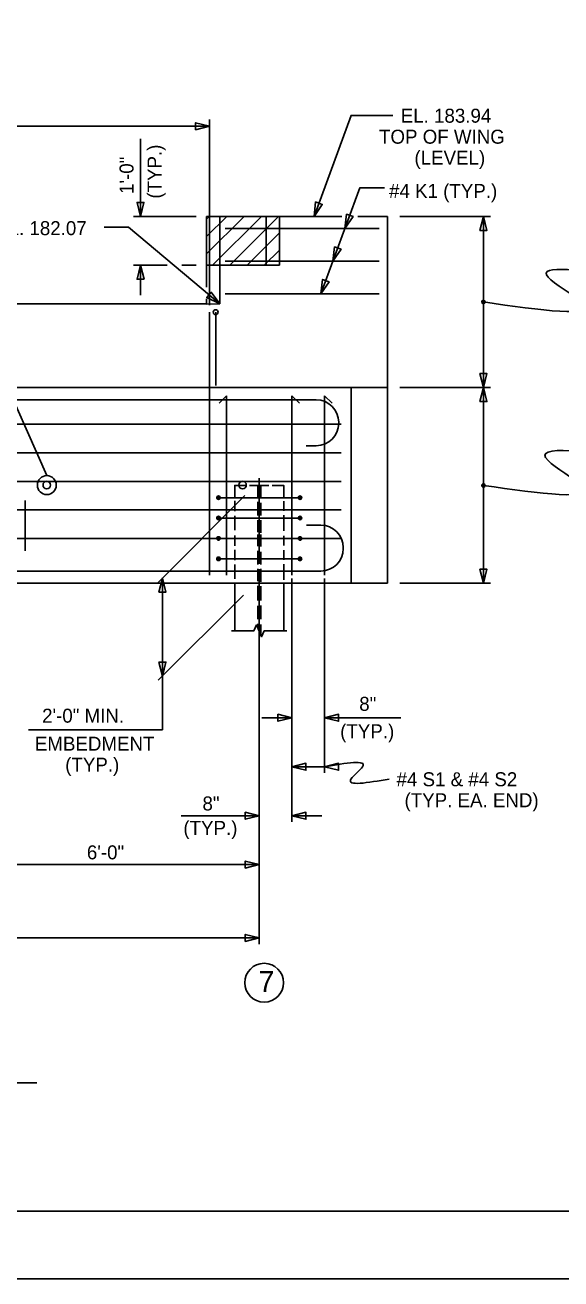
# Model space of a CAD drawing. Extents: x -41 to 191, y -168 to 6.
# Drawn here: x 160.78 to 171.73, y -50.47 to -24.84 of the extents above; entities that cross this region are included whole.
import ezdxf

# ---------------------------------------------------------------- set-up
doc = ezdxf.new("R2010")
doc.units = 0
for name, color, linetype in [('Arrowhead Terminators CELL', 7, 'Continuous'), ('Dimension Lines', 7, 'Continuous'), ('Dimension Lines CELL', 7, 'Continuous'), ('Mis Object Lines', 7, 'Continuous'), ('Plan Sheet CELL', 7, 'Continuous'), ('Plot Shape CELL', 7, 'Continuous'), ('Rebar Lines', 7, 'Continuous'), ('Rebar Lines CELL', 7, 'Continuous'), ('Sub End Bent Cap Lines CELL', 7, 'Continuous'), ('Text', 7, 'Continuous'), ('Title Text', 7, 'Continuous')]:
    doc.layers.add(name, color=color, linetype=linetype)

# ---------------------------------------------------------------- blocks, each defined once
blk = doc.blocks.new('AH')
at = {"layer": 'Sub End Bent Cap Lines CELL'}
blk.add_lwpolyline([(0, 0), (-1.25, 0.31), (-1.25, -0.31)], close=True, dxfattribs=at)

msp = doc.modelspace()

# ---------------------------------------------------------------- linework, layer by layer
at = {"layer": 'Arrowhead Terminators CELL'}
for points in [[(164.551, -26.909), (164.265, -26.98), (164.265, -26.837)], [(166.687, -28.749), (166.719, -28.455), (166.853, -28.505)], [(167.318, -28.999), (167.35, -28.705), (167.484, -28.755)], [(167.073, -29.665), (167.105, -29.372), (167.239, -29.421)], [(163.14, -29.749), (163.212, -30.036), (163.069, -30.036)], [(166.828, -30.332), (166.86, -30.039), (166.994, -30.088)], [(164.759, -30.54), (164.494, -30.41), (164.587, -30.301)], [(170.147, -32.249), (170.219, -31.962), (170.075, -31.962)], [(170.147, -32.249), (170.075, -32.535), (170.219, -32.535)], [(170.147, -36.249), (170.219, -35.962), (170.075, -35.962)], [(163.587, -36.142), (163.516, -36.428), (163.659, -36.428)], [(163.587, -38.144), (163.659, -37.858), (163.516, -37.858)], [(166.233, -38.999), (165.947, -39.07), (165.947, -38.927)], [(166.9, -38.999), (167.186, -39.07), (167.186, -38.927)], [(166.233, -39.999), (166.519, -40.07), (166.519, -39.927)], [(166.9, -39.999), (167.186, -40.07), (167.186, -39.927)], [(165.566, -40.999), (165.28, -41.07), (165.28, -40.927)], [(166.233, -40.999), (166.519, -40.927), (166.519, -41.07)], [(165.566, -41.998), (165.28, -41.926), (165.28, -42.069)], [(165.566, -43.498), (165.28, -43.426), (165.28, -43.569)]]:
    msp.add_lwpolyline(points, close=True, dxfattribs=at)
at = {"layer": 'Dimension Lines'}
for p, q in [((148.448, -26.909), (164.521, -26.909)), ((149.531, -26.909), (164.551, -26.909)), ((164.551, -30.564), (164.551, -26.766)), ((163.14, -27.166), (163.14, -28.749)), ((164.278, -28.749), (162.997, -28.749)), ((164.491, -29.16), (164.903, -28.749)), ((164.491, -28.806), (164.549, -28.749)), ((164.491, -29.513), (165.256, -28.749)), ((164.61, -29.749), (165.61, -28.749)), ((164.963, -29.749), (165.963, -28.749)), ((168.442, -28.749), (170.29, -28.749)), ((170.147, -28.749), (170.147, -32.249)), ((165.317, -29.749), (165.979, -29.086)), ((165.67, -29.749), (165.979, -29.44)), ((163.687, -29.749), (162.997, -29.749)), ((163.14, -29.749), (163.14, -30.357)), ((164.278, -29.749), (163.981, -29.749)), ((160.22, -31.784), (161.225, -34.049)), ((168.442, -32.249), (170.29, -32.249)), ((170.147, -36.249), (170.147, -32.249)), ((160.781, -35.588), (160.781, -34.56)), ((165.272, -34.457), (163.499, -36.23)), ((163.587, -39.241), (163.587, -36.142)), ((165.566, -36.249), (165.566, -43.623)), ((166.233, -36.154), (166.233, -41.124)), ((166.9, -36.154), (166.9, -40.124)), ((168.442, -36.249), (170.29, -36.249)), ((165.242, -36.489), (163.499, -38.232)), ((166.233, -38.999), (165.618, -38.999)), ((166.9, -38.999), (168.463, -38.999)), ((160.853, -39.241), (163.587, -39.241)), ((166.9, -39.999), (166.233, -39.999)), ((165.566, -40.999), (163.968, -40.999)), ((166.848, -40.999), (166.233, -40.999)), ((159.566, -41.998), (165.566, -41.998)), ((165.566, -43.498), (159.566, -43.498)), ((161.023, -46.457), (136.321, -46.457))]:
    msp.add_line(p, q, dxfattribs=at)
for points in [[(166.687, -28.749), (167.444, -26.687), (168.299, -26.687)], [(166.828, -30.332), (167.624, -28.166), (168.124, -28.166)], [(164.759, -30.54), (162.896, -28.97), (162.396, -28.97)]]:
    msp.add_lwpolyline(points, dxfattribs=at)
for centre, radius in [((161.225, -34.242), 0.193), ((165.666, -44.413), 0.397)]:
    msp.add_circle(centre, radius, dxfattribs=at)
for points in [[(173.186, -29.991), (171.467, -29.991), (172.144, -30.499), (170.147, -30.499)], [(173.587, -33.741), (171.467, -33.741), (172.144, -34.249), (170.147, -34.249)], [(166.9, -39.999), (167.678, -39.999), (167.441, -40.249), (168.22, -40.249)]]:
    msp.add_spline(points, degree=3, dxfattribs=at)
at = {"layer": 'Dimension Lines CELL'}
for centre in [(170.147, -30.499), (170.147, -34.249)]:
    msp.add_circle(centre, 0.0353, dxfattribs=at)
at = {"layer": 'Mis Object Lines'}
for p, q in [((164.491, -28.749), (167.252, -28.749)), ((164.491, -30.195), (164.491, -28.749)), ((164.759, -30.54), (164.759, -28.748)), ((165.711, -29.748), (165.711, -28.748)), ((165.979, -29.748), (165.979, -28.748)), ((168.185, -28.749), (167.584, -28.749)), ((168.185, -28.749), (168.185, -36.249)), ((164.491, -29.749), (165.711, -29.749)), ((165.711, -29.749), (165.979, -29.748)), ((168.185, -29.749), (168.185, -36.249)), ((164.491, -30.54), (164.491, -30.437)), ((137.623, -30.54), (164.491, -30.54)), ((164.491, -30.541), (164.759, -30.54)), ((147.948, -32.249), (168.185, -32.249)), ((167.448, -32.249), (167.448, -36.249)), ((133.764, -36.249), (168.185, -36.249))]:
    msp.add_line(p, q, dxfattribs=at)
at = {"layer": 'Plan Sheet CELL'}
msp.add_line((118.128, -49.079), (191.409, -49.079), dxfattribs=at)
at = {"layer": 'Plot Shape CELL'}
msp.add_lwpolyline([(115.715, -0.087), (191.429, -0.087), (191.429, -50.467), (115.715, -50.467)], close=True, dxfattribs=at)
at = {"layer": 'Rebar Lines'}
for p, q in [((168.018, -28.999), (164.869, -28.999)), ((168.018, -29.665), (164.869, -29.665)), ((168.018, -30.332), (164.869, -30.332)), ((164.551, -30.938), (164.551, -30.707)), ((164.676, -30.955), (164.676, -30.707)), ((164.551, -36.082), (164.551, -30.938)), ((164.676, -32.207), (164.676, -30.955)), ((127.69, -32.5), (166.732, -32.5)), ((164.9, -32.415), (164.746, -32.569)), ((164.9, -36.082), (164.9, -32.415)), ((166.387, -32.569), (166.233, -32.415)), ((166.233, -32.415), (166.233, -36.082)), ((166.9, -32.415), (166.9, -36.082)), ((167.053, -32.569), (166.9, -32.415)), ((149.253, -32.999), (167.24, -32.999)), ((149.253, -33.582), (167.24, -33.582)), ((149.253, -34.165), (167.24, -34.165)), ((165.535, -34.491), (165.535, -34.249)), ((165.566, -34.097), (165.566, -35.854)), ((165.598, -34.497), (165.598, -34.249)), ((165.535, -34.863), (165.535, -34.584)), ((149.253, -34.749), (167.24, -34.749)), ((165.598, -34.863), (165.598, -34.607)), ((165.535, -35.206), (165.535, -34.956)), ((165.598, -35.217), (165.598, -34.956)), ((149.253, -35.332), (167.24, -35.332)), ((165.535, -35.491), (165.535, -35.249)), ((165.598, -35.497), (165.598, -35.249)), ((165.535, -35.863), (165.535, -35.584)), ((165.598, -35.863), (165.598, -35.607)), ((127.69, -35.999), (166.825, -35.999)), ((165.535, -36.206), (165.535, -35.956)), ((165.566, -35.958), (165.566, -36.249)), ((165.598, -36.217), (165.598, -35.956)), ((165.066, -36.266), (165.066, -37.218)), ((165.535, -36.601), (165.535, -36.304)), ((165.566, -36.318), (165.566, -37.524)), ((165.598, -36.601), (165.598, -36.31)), ((166.067, -36.266), (166.067, -37.218)), ((165.535, -36.984), (165.535, -36.711)), ((165.598, -36.984), (165.598, -36.705)), ((165.535, -37.152), (165.535, -37.077)), ((165.598, -37.301), (165.598, -37.089))]:
    msp.add_line(p, q, dxfattribs=at)
for points in [[(165.066, -34.482), (165.066, -34.249), (165.289, -34.249)], [(165.364, -34.249), (165.764, -34.249)], [(165.833, -34.249), (166.066, -34.249), (166.066, -34.495)], [(165.066, -34.773), (165.066, -34.565)], [(166.066, -34.571), (166.066, -34.77)], [(165.066, -35.16), (165.066, -34.868)], [(166.066, -34.855), (166.066, -35.176)], [(165.066, -35.482), (165.066, -35.274)], [(166.066, -35.28), (166.066, -35.479)], [(165.066, -35.773), (165.066, -35.565)], [(166.066, -35.571), (166.066, -35.77)], [(165.066, -36.16), (165.066, -35.868)], [(166.066, -35.855), (166.066, -36.176)], [(164.996, -37.218), (165.458, -37.218), (165.513, -37.098), (165.615, -37.343), (165.667, -37.218), (166.133, -37.218)]]:
    msp.add_lwpolyline(points, dxfattribs=at)
msp.add_circle((164.676, -30.707), 0.0495, dxfattribs=at)
at = {"layer": 'Rebar Lines CELL'}
for p, q in [((167.191, -32.979), (167.191, -32.958)), ((166.524, -33.437), (166.732, -33.437)), ((166.4, -34.499), (164.733, -34.499)), ((166.4, -34.915), (164.733, -34.915)), ((166.533, -35.061), (166.825, -35.061)), ((166.4, -35.332), (164.733, -35.332)), ((167.284, -35.519), (167.284, -35.54)), ((166.4, -35.749), (164.733, -35.749))]:
    msp.add_line(p, q, dxfattribs=at)
for points in [[(164.733, -34.463), (164.72, -34.466), (164.708, -34.474), (164.7, -34.485), (164.698, -34.499), (164.7, -34.512), (164.708, -34.523), (164.72, -34.531), (164.733, -34.534), (164.746, -34.531), (164.758, -34.523), (164.766, -34.512), (164.768, -34.499), (164.766, -34.485), (164.758, -34.474), (164.747, -34.466), (164.733, -34.463), (164.733, -34.499), (164.733, -34.534), (164.72, -34.531), (164.733, -34.499), (164.708, -34.523), (164.7, -34.512), (164.733, -34.499), (164.698, -34.499), (164.7, -34.485), (164.733, -34.499), (164.708, -34.474), (164.72, -34.466), (164.733, -34.499), (164.747, -34.466), (164.758, -34.474), (164.733, -34.499), (164.766, -34.485), (164.768, -34.499), (164.733, -34.499), (164.766, -34.512), (164.758, -34.523), (164.733, -34.499), (164.746, -34.531)], [(166.4, -34.463), (166.386, -34.466), (166.375, -34.474), (166.367, -34.485), (166.365, -34.499), (166.367, -34.512), (166.375, -34.523), (166.386, -34.531), (166.4, -34.534), (166.413, -34.531), (166.425, -34.523), (166.432, -34.512), (166.435, -34.499), (166.432, -34.485), (166.425, -34.474), (166.413, -34.466), (166.4, -34.463), (166.4, -34.499), (166.4, -34.534), (166.386, -34.531), (166.4, -34.499), (166.375, -34.523), (166.367, -34.512), (166.4, -34.499), (166.365, -34.499), (166.367, -34.485), (166.4, -34.499), (166.375, -34.474), (166.386, -34.466), (166.4, -34.499), (166.413, -34.466), (166.425, -34.474), (166.4, -34.499), (166.432, -34.485), (166.435, -34.499), (166.4, -34.499), (166.432, -34.512), (166.425, -34.523), (166.4, -34.499), (166.413, -34.531)], [(164.733, -34.88), (164.72, -34.883), (164.708, -34.89), (164.7, -34.902), (164.698, -34.915), (164.7, -34.929), (164.708, -34.94), (164.72, -34.948), (164.733, -34.95), (164.746, -34.948), (164.758, -34.94), (164.766, -34.929), (164.768, -34.915), (164.766, -34.902), (164.758, -34.89), (164.747, -34.883), (164.733, -34.88), (164.733, -34.915), (164.733, -34.95), (164.72, -34.948), (164.733, -34.915), (164.708, -34.94), (164.7, -34.929), (164.733, -34.915), (164.698, -34.915), (164.7, -34.902), (164.733, -34.915), (164.708, -34.89), (164.72, -34.883), (164.733, -34.915), (164.747, -34.883), (164.758, -34.89), (164.733, -34.915), (164.766, -34.902), (164.768, -34.915), (164.733, -34.915), (164.766, -34.929), (164.758, -34.94), (164.733, -34.915), (164.746, -34.948)], [(166.4, -34.88), (166.386, -34.883), (166.375, -34.89), (166.367, -34.902), (166.365, -34.915), (166.367, -34.929), (166.375, -34.94), (166.386, -34.948), (166.4, -34.95), (166.413, -34.948), (166.425, -34.94), (166.432, -34.929), (166.435, -34.915), (166.432, -34.902), (166.425, -34.89), (166.413, -34.883), (166.4, -34.88), (166.4, -34.915), (166.4, -34.95), (166.386, -34.948), (166.4, -34.915), (166.375, -34.94), (166.367, -34.929), (166.4, -34.915), (166.365, -34.915), (166.367, -34.902), (166.4, -34.915), (166.375, -34.89), (166.386, -34.883), (166.4, -34.915), (166.413, -34.883), (166.425, -34.89), (166.4, -34.915), (166.432, -34.902), (166.435, -34.915), (166.4, -34.915), (166.432, -34.929), (166.425, -34.94), (166.4, -34.915), (166.413, -34.948)], [(164.733, -35.297), (164.72, -35.299), (164.708, -35.307), (164.7, -35.318), (164.698, -35.332), (164.7, -35.345), (164.708, -35.357), (164.72, -35.364), (164.733, -35.367), (164.746, -35.364), (164.758, -35.357), (164.766, -35.345), (164.768, -35.332), (164.766, -35.318), (164.758, -35.307), (164.747, -35.299), (164.733, -35.297), (164.733, -35.332), (164.733, -35.367), (164.72, -35.364), (164.733, -35.332), (164.708, -35.357), (164.7, -35.345), (164.733, -35.332), (164.698, -35.332), (164.7, -35.318), (164.733, -35.332), (164.708, -35.307), (164.72, -35.299), (164.733, -35.332), (164.747, -35.299), (164.758, -35.307), (164.733, -35.332), (164.766, -35.318), (164.768, -35.332), (164.733, -35.332), (164.766, -35.345), (164.758, -35.357), (164.733, -35.332), (164.746, -35.364)], [(166.4, -35.297), (166.386, -35.299), (166.375, -35.307), (166.367, -35.318), (166.365, -35.332), (166.367, -35.345), (166.375, -35.357), (166.386, -35.364), (166.4, -35.367), (166.413, -35.364), (166.425, -35.357), (166.432, -35.345), (166.435, -35.332), (166.432, -35.318), (166.425, -35.307), (166.413, -35.299), (166.4, -35.297), (166.4, -35.332), (166.4, -35.367), (166.386, -35.364), (166.4, -35.332), (166.375, -35.357), (166.367, -35.345), (166.4, -35.332), (166.365, -35.332), (166.367, -35.318), (166.4, -35.332), (166.375, -35.307), (166.386, -35.299), (166.4, -35.332), (166.413, -35.299), (166.425, -35.307), (166.4, -35.332), (166.432, -35.318), (166.435, -35.332), (166.4, -35.332), (166.432, -35.345), (166.425, -35.357), (166.4, -35.332), (166.413, -35.364)], [(164.733, -35.713), (164.72, -35.716), (164.708, -35.724), (164.7, -35.735), (164.698, -35.749), (164.7, -35.762), (164.708, -35.773), (164.72, -35.781), (164.733, -35.784), (164.746, -35.781), (164.758, -35.773), (164.766, -35.762), (164.768, -35.749), (164.766, -35.735), (164.758, -35.724), (164.747, -35.716), (164.733, -35.713), (164.733, -35.749), (164.733, -35.784), (164.72, -35.781), (164.733, -35.749), (164.708, -35.773), (164.7, -35.762), (164.733, -35.749), (164.698, -35.749), (164.7, -35.735), (164.733, -35.749), (164.708, -35.724), (164.72, -35.716), (164.733, -35.749), (164.747, -35.716), (164.758, -35.724), (164.733, -35.749), (164.766, -35.735), (164.768, -35.749), (164.733, -35.749), (164.766, -35.762), (164.758, -35.773), (164.733, -35.749), (164.746, -35.781)], [(166.4, -35.713), (166.386, -35.716), (166.375, -35.724), (166.367, -35.735), (166.365, -35.749), (166.367, -35.762), (166.375, -35.773), (166.386, -35.781), (166.4, -35.784), (166.413, -35.781), (166.425, -35.773), (166.432, -35.762), (166.435, -35.749), (166.432, -35.735), (166.425, -35.724), (166.413, -35.716), (166.4, -35.713), (166.4, -35.749), (166.4, -35.784), (166.386, -35.781), (166.4, -35.749), (166.375, -35.773), (166.367, -35.762), (166.4, -35.749), (166.365, -35.749), (166.367, -35.735), (166.4, -35.749), (166.375, -35.724), (166.386, -35.716), (166.4, -35.749), (166.413, -35.716), (166.425, -35.724), (166.4, -35.749), (166.432, -35.735), (166.435, -35.749), (166.4, -35.749), (166.432, -35.762), (166.425, -35.773), (166.4, -35.749), (166.413, -35.781)]]:
    msp.add_lwpolyline(points, dxfattribs=at)
for centre in [(161.225, -34.242), (165.225, -34.242)]:
    msp.add_circle(centre, 0.0773, dxfattribs=at)
for centre, start, end in [((166.732, -32.958), 0, 90), ((166.732, -32.979), 270, 0), ((166.825, -35.519), 0, 90), ((166.825, -35.54), 270, 0)]:
    msp.add_arc(centre, 0.458, start, end, dxfattribs=at)

# ---------------------------------------------------------------- block references
at = {"layer": 'Arrowhead Terminators CELL', "xscale": 0.2288}
for p, yscale, rotation in [((163.14, -28.749), -0.2288, -90), ((170.147, -28.749), 0.2288, 90)]:
    msp.add_blockref('AH', p, dxfattribs=dict(at, yscale=yscale, rotation=rotation))

# ---------------------------------------------------------------- texts
at = {"layer": 'Text'}
for s, p in [('EL. 183.94', (168.458, -26.835)), ('TOP OF WING', (168.014, -27.264)), ('(LEVEL)', (168.738, -27.693)), ('#4 K1 (TYP.)', (168.219, -28.373)), ('EL. 182.07', (160.19, -29.133)), ('8"', (167.61, -38.856)), ('2\'-0" MIN.', (161.129, -39.098)), ('(TYP.)', (167.22, -39.416)), ('EMBEDMENT', (160.981, -39.67)), ('(TYP.)', (161.601, -40.099)), ('#4 S1 & #4 S2', (168.372, -40.397)), ('8"', (164.406, -40.892)), ('(TYP. EA. END)', (168.535, -40.826)), ('(TYP.)', (164.016, -41.392)), ('6\'-0"', (162.044, -41.891))]:
    msp.add_text(s, height=0.286, dxfattribs=at).set_placement(p)
for s, p in [('(TYP.)', (163.569, -28.387)), ('1\'-0"', (162.997, -28.291))]:
    msp.add_text(s, height=0.286, rotation=90, dxfattribs=at).set_placement(p)
at = {"layer": 'Title Text'}
msp.add_text('7', height=0.429, dxfattribs=at).set_placement((165.554, -44.605))

doc.saveas('drawing.dxf')
